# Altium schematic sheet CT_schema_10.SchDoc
size 147 x 119 mm
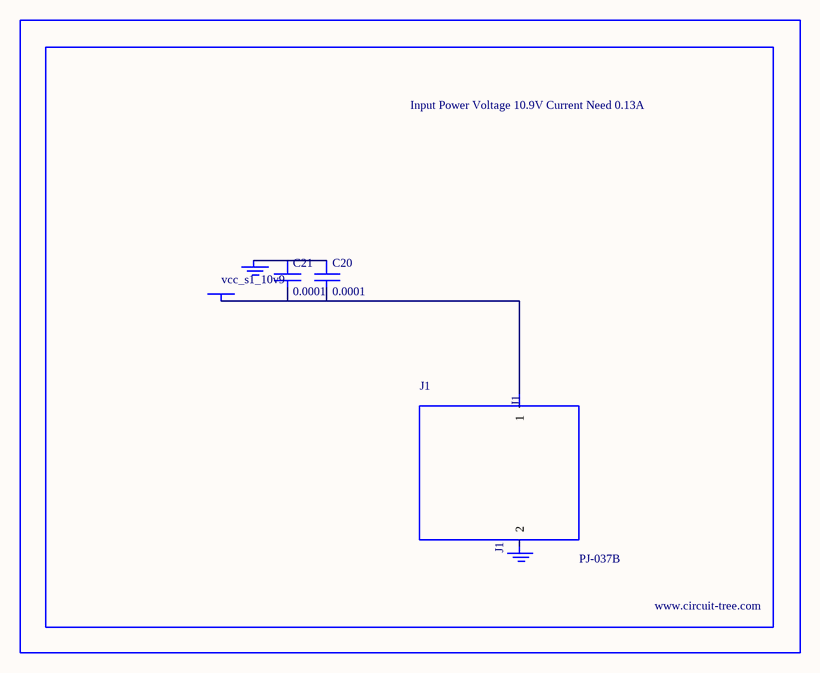
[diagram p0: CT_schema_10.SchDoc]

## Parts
BORDER9  (no value)
C20  0.0001  [EXV-9H]
C21  0.0001  [EXV-9H]
GND_INSTANCE_9_0  (no value)
GND_INSTANCE_9_1  (no value)
J1  PJ-037B  [PJ-037B_PACKAGE]
POWER_INSTANCE_9_0  vcc_s1_10v9

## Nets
NetC20_1: C20.1 C21.1 GND_INSTANCE_9_0.0(GND)
NetC20_2: C20.2 C21.2 J1.1 POWER_INSTANCE_9_0.0(PWR)

Not connected (* = marked no-connect by the designer): GND_INSTANCE_9_1 0(GND); J1 2

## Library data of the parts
BORDER9 = BORDER_PAGE9
C20 C21 = EDK107M035A9HAA
GND_INSTANCE_9_0 GND_INSTANCE_9_1 = GND
POWER_INSTANCE_9_0 = PWR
